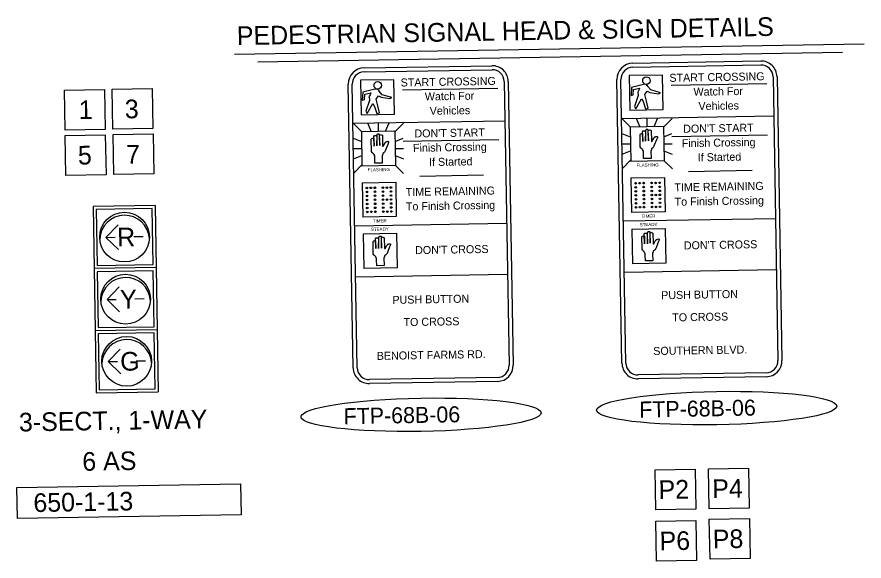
# Model space of a CAD drawing. Extents: x 924596 to 926137, y 853397 to 853834.
# Drawn here: x 925476.3 to 925603.4, y 853695.8 to 853777.4 of the extents above; entities that cross this region are included whole.
import ezdxf

# ---------------------------------------------------------------- set-up
doc = ezdxf.new("R2010")
doc.units = 0
for name, color, linetype in [('NorthArw_dp', 7, 'Continuous'), ('Scale_dp', 7, 'Continuous'), ('SignalHead', 7, 'Continuous'), ('SignPanel', 7, 'Continuous'), ('TextTables', 7, 'Continuous')]:
    doc.layers.add(name, color=color, linetype=linetype)

msp = doc.modelspace()

# ---------------------------------------------------------------- linework, layer by layer
at = {"layer": 'NorthArw_dp'}
for p, q in [((925572.03, 853709.51), (925578.03, 853709.61)), ((925572.14, 853703.51), (925572.03, 853709.51)), ((925578.03, 853709.61), (925578.14, 853703.61)), ((925580.03, 853709.65), (925586.03, 853709.75)), ((925580.14, 853703.65), (925580.03, 853709.65)), ((925586.03, 853709.75), (925586.14, 853703.75)), ((925578.14, 853703.61), (925572.14, 853703.51)), ((925586.14, 853703.75), (925580.14, 853703.65)), ((925572.15, 853701.81), (925578.15, 853701.92)), ((925572.26, 853695.82), (925572.15, 853701.81)), ((925578.15, 853701.92), (925578.26, 853695.92)), ((925580.16, 853702.1), (925586.16, 853702.2)), ((925580.27, 853696.1), (925580.16, 853702.1)), ((925586.16, 853702.2), (925586.26, 853696.2)), ((925586.26, 853696.2), (925580.27, 853696.1)), ((925578.26, 853695.92), (925572.26, 853695.82))]:
    msp.add_line(p, q, dxfattribs=at)
at = {"layer": 'Scale_dp'}
for centre in [(925581.26, 853718.76), (925536.93, 853717.76)]:
    msp.add_ellipse(centre, major_axis=(18, 0.31), ratio=0.138889, dxfattribs=at)
at = {"layer": 'SignalHead'}
for p, q in [((925483.46, 853766.46), (925489.46, 853766.57)), ((925483.57, 853760.47), (925483.46, 853766.46)), ((925489.46, 853766.57), (925489.57, 853760.57)), ((925490.63, 853766.59), (925496.62, 853766.69)), ((925490.73, 853760.59), (925490.63, 853766.59)), ((925496.62, 853766.69), (925496.73, 853760.69)), ((925489.57, 853760.57), (925483.57, 853760.47)), ((925483.58, 853759.65), (925489.58, 853759.76)), ((925483.69, 853753.65), (925483.58, 853759.65)), ((925489.58, 853759.76), (925489.69, 853753.76)), ((925496.73, 853760.69), (925490.73, 853760.59)), ((925490.75, 853759.78), (925496.74, 853759.88)), ((925490.85, 853753.78), (925490.75, 853759.78)), ((925496.74, 853759.88), (925496.85, 853753.88)), ((925489.69, 853753.76), (925483.69, 853753.65)), ((925496.85, 853753.88), (925490.85, 853753.78)), ((925497.05, 853749.15), (925487.74, 853748.99)), ((925487.74, 853748.99), (925488.21, 853721.04)), ((925496.6, 853748.68), (925488.21, 853748.54)), ((925488.21, 853748.54), (925488.35, 853740.15)), ((925496.74, 853740.29), (925496.6, 853748.68)), ((925497.05, 853749.15), (925497.53, 853721.2)), ((925489.68, 853744.37), (925491.51, 853746.26)), ((925489.68, 853744.37), (925491.08, 853744.39)), ((925489.68, 853744.37), (925491.57, 853742.53)), ((925495.27, 853744.46), (925493.87, 853744.44)), ((925497.21, 853739.83), (925487.89, 853739.68)), ((925488.35, 853740.15), (925496.74, 853740.29)), ((925496.75, 853739.36), (925488.37, 853739.22)), ((925488.37, 853739.22), (925488.51, 853730.83)), ((925496.9, 853730.97), (925496.75, 853739.36)), ((925489.84, 853735.05), (925491.67, 853736.94)), ((925489.84, 853735.05), (925491.23, 853735.07)), ((925489.84, 853735.05), (925491.73, 853733.22)), ((925495.43, 853735.14), (925494.03, 853735.12)), ((925497.37, 853730.52), (925488.05, 853730.36)), ((925488.51, 853730.83), (925496.9, 853730.97)), ((925496.91, 853730.04), (925488.53, 853729.9)), ((925488.53, 853729.9), (925488.67, 853721.51)), ((925497.06, 853721.65), (925496.91, 853730.04)), ((925490, 853725.73), (925491.83, 853727.62)), ((925490, 853725.73), (925491.39, 853725.75)), ((925490, 853725.73), (925491.89, 853723.9)), ((925495.59, 853725.82), (925494.19, 853725.8)), ((925488.67, 853721.51), (925497.06, 853721.65)), ((925488.21, 853721.04), (925497.53, 853721.2)), ((925476.33, 853706.85), (925509.88, 853707.42)), ((925509.88, 853707.42), (925509.96, 853702.77)), ((925476.41, 853702.19), (925476.33, 853706.85)), ((925509.96, 853702.77), (925476.41, 853702.19))]:
    msp.add_line(p, q, dxfattribs=at)
for centre in [(925492.47, 853744.41), (925492.63, 853735.1), (925492.79, 853725.78)]:
    msp.add_circle(centre, 3.73, dxfattribs=at)
for centre in [(925492.48, 853743.95), (925492.64, 853734.63), (925492.8, 853725.31)]:
    msp.add_arc(centre, 3.73, 4.5574, 177.3908, dxfattribs=at)
at = {"layer": 'SignPanel'}
for p, q in [((925528.38, 853769.79), (925547.57, 853770.12)), ((925568.67, 853770.49), (925587.87, 853770.83)), ((925568.68, 853769.89), (925587.88, 853770.23)), ((925528.39, 853769.19), (925547.58, 853769.52)), ((925568.14, 853768.64), (925568.23, 853763.45)), ((925589.71, 853768.46), (925590.45, 853725.9)), ((925590.31, 853768.47), (925591.05, 853725.92)), ((925526.76, 853724.79), (925526.02, 853767.35)), ((925527.36, 853724.8), (925526.62, 853767.36)), ((925527.85, 853767.93), (925527.94, 853762.75)), ((925549.41, 853767.75), (925550.15, 853725.2)), ((925550.01, 853767.76), (925550.75, 853725.21)), ((925567.05, 853725.5), (925566.31, 853768.05)), ((925567.65, 853725.51), (925566.91, 853768.06)), ((925574.43, 853767.19), (925588.77, 853767.44)), ((925534.13, 853766.48), (925548.47, 853766.73)), ((925567.02, 853762.18), (925589.81, 853762.58)), ((925567.05, 853762.18), (925568.28, 853760.96)), ((925569.76, 853760.98), (925569.25, 853762.22)), ((925570.83, 853761), (925570.83, 853762.25)), ((925571.91, 853761.02), (925572.43, 853762.28)), ((925573.3, 853760.88), (925574.61, 853762.2)), ((925526.72, 853761.48), (925549.52, 853761.87)), ((925526.75, 853761.48), (925527.98, 853760.25)), ((925529.47, 853760.28), (925528.95, 853761.52)), ((925530.53, 853760.3), (925530.53, 853761.54)), ((925531.61, 853760.32), (925532.13, 853761.57)), ((925533, 853760.18), (925534.31, 853761.49)), ((925568.28, 853760.96), (925573.3, 853761.04)), ((925573.3, 853761.04), (925573.39, 853755.86)), ((925527.98, 853760.25), (925533, 853760.34)), ((925533, 853760.34), (925533.09, 853755.16)), ((925567.05, 853759.97), (925568.3, 853759.45)), ((925573.32, 853759.45), (925574.56, 853759.96)), ((925574.56, 853759.51), (925588.9, 853759.76)), ((925526.76, 853759.26), (925528.01, 853758.75)), ((925533.03, 853758.74), (925534.26, 853759.25)), ((925534.27, 853758.81), (925548.61, 853759.05)), ((925567.08, 853758.4), (925568.32, 853758.41)), ((925573.34, 853758.41), (925574.58, 853758.41)), ((925526.79, 853757.7), (925528.02, 853757.7)), ((925533.05, 853757.71), (925534.29, 853757.71)), ((925567.11, 853756.86), (925568.34, 853757.37)), ((925573.36, 853757.37), (925574.61, 853756.85)), ((925526.81, 853756.16), (925528.04, 853756.67)), ((925533.07, 853756.66), (925534.31, 853756.15)), ((925567.15, 853754.71), (925568.36, 853755.93)), ((925573.39, 853755.86), (925568.37, 853755.77)), ((925573.39, 853755.86), (925574.62, 853754.63)), ((925526.85, 853754.01), (925528.07, 853755.23)), ((925533.09, 853755.16), (925528.07, 853755.07)), ((925533.09, 853755.16), (925534.32, 853753.93)), ((925577.05, 853754.27), (925586.59, 853754.44)), ((925536.76, 853753.57), (925546.3, 853753.73)), ((925568.41, 853753.28), (925573.43, 853753.37)), ((925573.43, 853753.37), (925573.52, 853748.18)), ((925528.11, 853752.57), (925533.13, 853752.66)), ((925533.13, 853752.66), (925533.22, 853747.48)), ((925573.52, 853748.18), (925568.5, 853748.09)), ((925533.22, 853747.48), (925528.2, 853747.39)), ((925567.28, 853746.83), (925590.08, 853747.22)), ((925526.99, 853746.12), (925549.78, 853746.52)), ((925568.54, 853745.6), (925573.56, 853745.69)), ((925573.56, 853745.69), (925573.65, 853740.5)), ((925528.25, 853744.89), (925533.27, 853744.98)), ((925533.27, 853744.98), (925533.36, 853739.8)), ((925573.65, 853740.5), (925568.63, 853740.42)), ((925533.36, 853739.8), (925528.34, 853739.71)), ((925567.42, 853739.15), (925590.21, 853739.54)), ((925527.12, 853738.44), (925549.92, 853738.84)), ((925588.68, 853724.07), (925569.48, 853723.74)), ((925548.38, 853723.37), (925529.19, 853723.04)), ((925548.39, 853722.77), (925529.2, 853722.44)), ((925588.69, 853723.47), (925569.49, 853723.14))]:
    msp.add_line(p, q, dxfattribs=at)
for points in [[(925573.16, 853768.72), (925568.14, 853768.64)], [(925573.25, 853763.54), (925573.16, 853768.72)], [(925532.87, 853768.02), (925527.85, 853767.93)], [(925532.96, 853762.84), (925532.87, 853768.02)], [(925568.23, 853763.45), (925573.25, 853763.54)], [(925527.94, 853762.75), (925532.96, 853762.84)], [(925568.28, 853760.96), (925568.37, 853755.77)], [(925527.98, 853760.25), (925528.07, 853755.07)], [(925568.41, 853753.28), (925568.5, 853748.09)], [(925528.11, 853752.57), (925528.2, 853747.39)], [(925568.54, 853745.6), (925568.63, 853740.42)], [(925528.25, 853744.89), (925528.34, 853739.71)]]:
    msp.add_lwpolyline(points, dxfattribs=at)
for points in [[(925570.69, 853767.33), (925570.31, 853767.32), (925568.49, 853766.86), (925568.42, 853765.66), (925568.75, 853765.76), (925568.79, 853766.57), (925569.7, 853766.73), (925569.65, 853766.59), (925569.61, 853766.44), (925569.42, 853766.15), (925569.42, 853766.01), (925569.47, 853765.91), (925569.47, 853765.82), (925569.48, 853765.67), (925569.48, 853765.63), (925568.93, 853763.98), (925569.13, 853763.65), (925570.01, 853765.16), (925570.26, 853764.73), (925570.61, 853763.63), (925571, 853763.73), (925570.74, 853764.78), (925570.48, 853765.79), (925570.86, 853766.32), (925571.24, 853766.09), (925572.54, 853765.92), (925572.83, 853766.07), (925571.38, 853766.48), (925570.94, 853767), (925570.94, 853767.09), (925570.89, 853767.09), (925570.89, 853767.09)], [(925530.4, 853766.62), (925530.02, 853766.62), (925528.2, 853766.15), (925528.12, 853764.95), (925528.46, 853765.05), (925528.49, 853765.87), (925529.4, 853766.03), (925529.36, 853765.88), (925529.31, 853765.74), (925529.12, 853765.45), (925529.13, 853765.3), (925529.18, 853765.21), (925529.18, 853765.11), (925529.18, 853764.97), (925529.18, 853764.92), (925528.63, 853763.28), (925528.83, 853762.95), (925529.72, 853764.45), (925529.96, 853764.02), (925530.32, 853762.93), (925530.7, 853763.03), (925530.44, 853764.08), (925530.19, 853765.08), (925530.56, 853765.62), (925530.95, 853765.38), (925532.25, 853765.22), (925532.53, 853765.36), (925531.09, 853765.77), (925530.64, 853766.29), (925530.64, 853766.39), (925530.6, 853766.39), (925530.6, 853766.39)], [(925530.02, 853755.48), (925530, 853756.34), (925530, 853756.58), (925529.9, 853756.73), (925529.9, 853756.82), (925529.8, 853756.92), (925529.65, 853757.01), (925529.6, 853757.1), (925529.51, 853757.25), (925529.5, 853757.34), (925529.47, 853759.12), (925529.57, 853759.22), (925529.57, 853759.22), (925529.71, 853759.27), (925529.76, 853759.22), (925529.86, 853759.22), (925529.86, 853759.17), (925529.88, 853758.07), (925529.85, 853759.51), (925529.94, 853759.65), (925530.09, 853759.66), (925530.14, 853759.66), (925530.28, 853759.56), (925530.31, 853758.08), (925530.33, 853759.71), (925530.37, 853759.85), (925530.47, 853759.9), (925530.61, 853759.91), (925530.66, 853759.86), (925530.66, 853759.76), (925530.74, 853758.13), (925530.71, 853759.67), (925530.76, 853759.72), (925530.85, 853759.77), (925531, 853759.82), (925531.05, 853759.72), (925531.14, 853759.68), (925531.17, 853758.14), (925531.17, 853758.04), (925531.17, 853758.04), (925531.27, 853758.05), (925531.27, 853758.05), (925531.55, 853758.53), (925531.64, 853758.63), (925531.64, 853758.68), (925531.69, 853758.72), (925531.78, 853758.73), (925531.83, 853758.77), (925532.02, 853758.78), (925532.07, 853758.73), (925532.07, 853758.73), (925532.07, 853758.68), (925532.07, 853758.64), (925532.07, 853758.59), (925531.94, 853758.3), (925531.61, 853757.47), (925531.57, 853757.33), (925531.43, 853757.14), (925531.33, 853757.04), (925531.19, 853756.94), (925531.19, 853756.84), (925531.1, 853756.6), (925531.12, 853755.5)], [(925570.31, 853756.18), (925570.3, 853757.05), (925570.29, 853757.29), (925570.19, 853757.43), (925570.19, 853757.53), (925570.1, 853757.62), (925569.95, 853757.71), (925569.9, 853757.81), (925569.8, 853757.95), (925569.8, 853758.05), (925569.77, 853759.82), (925569.86, 853759.92), (925569.86, 853759.92), (925570.01, 853759.97), (925570.06, 853759.92), (925570.15, 853759.93), (925570.15, 853759.88), (925570.17, 853758.77), (925570.15, 853760.21), (925570.24, 853760.36), (925570.38, 853760.36), (925570.43, 853760.36), (925570.58, 853760.27), (925570.6, 853758.78), (925570.62, 853760.41), (925570.67, 853760.56), (925570.76, 853760.61), (925570.91, 853760.61), (925570.96, 853760.56), (925570.96, 853760.47), (925571.03, 853758.84), (925571.01, 853760.37), (925571.05, 853760.42), (925571.15, 853760.47), (925571.29, 853760.52), (925571.34, 853760.43), (925571.44, 853760.38), (925571.47, 853758.84), (925571.47, 853758.75), (925571.47, 853758.75), (925571.56, 853758.75), (925571.56, 853758.75), (925571.84, 853759.23), (925571.94, 853759.33), (925571.94, 853759.38), (925571.98, 853759.43), (925572.08, 853759.43), (925572.13, 853759.48), (925572.32, 853759.48), (925572.37, 853759.44), (925572.37, 853759.44), (925572.37, 853759.39), (925572.37, 853759.34), (925572.37, 853759.29), (925572.23, 853759), (925571.91, 853758.18), (925571.86, 853758.03), (925571.72, 853757.84), (925571.63, 853757.74), (925571.49, 853757.64), (925571.49, 853757.55), (925571.4, 853757.31), (925571.42, 853756.2)], [(925530.28, 853740.12), (925530.27, 853740.99), (925530.26, 853741.23), (925530.17, 853741.37), (925530.16, 853741.46), (925530.07, 853741.56), (925529.92, 853741.65), (925529.87, 853741.75), (925529.77, 853741.89), (925529.77, 853741.98), (925529.74, 853743.76), (925529.83, 853743.86), (925529.83, 853743.86), (925529.98, 853743.91), (925530.03, 853743.86), (925530.12, 853743.86), (925530.12, 853743.82), (925530.14, 853742.71), (925530.12, 853744.15), (925530.21, 853744.3), (925530.35, 853744.3), (925530.4, 853744.3), (925530.55, 853744.21), (925530.57, 853742.72), (925530.59, 853744.35), (925530.64, 853744.5), (925530.73, 853744.55), (925530.88, 853744.55), (925530.93, 853744.5), (925530.93, 853744.41), (925531.01, 853742.77), (925530.98, 853744.31), (925531.03, 853744.36), (925531.12, 853744.41), (925531.26, 853744.46), (925531.31, 853744.36), (925531.41, 853744.32), (925531.44, 853742.78), (925531.44, 853742.69), (925531.44, 853742.69), (925531.53, 853742.69), (925531.53, 853742.69), (925531.81, 853743.17), (925531.91, 853743.27), (925531.91, 853743.32), (925531.95, 853743.37), (925532.05, 853743.37), (925532.1, 853743.42), (925532.29, 853743.42), (925532.34, 853743.37), (925532.34, 853743.37), (925532.34, 853743.33), (925532.34, 853743.28), (925532.34, 853743.23), (925532.2, 853742.94), (925531.88, 853742.12), (925531.84, 853741.97), (925531.69, 853741.78), (925531.6, 853741.68), (925531.46, 853741.58), (925531.46, 853741.49), (925531.37, 853741.24), (925531.39, 853740.14)], [(925570.58, 853740.83), (925570.56, 853741.69), (925570.56, 853741.93), (925570.46, 853742.07), (925570.46, 853742.17), (925570.36, 853742.26), (925570.22, 853742.36), (925570.17, 853742.45), (925570.07, 853742.59), (925570.07, 853742.69), (925570.04, 853744.47), (925570.13, 853744.56), (925570.13, 853744.56), (925570.27, 853744.61), (925570.32, 853744.57), (925570.42, 853744.57), (925570.42, 853744.52), (925570.44, 853743.42), (925570.41, 853744.86), (925570.51, 853745), (925570.65, 853745), (925570.7, 853745), (925570.84, 853744.91), (925570.87, 853743.42), (925570.89, 853745.06), (925570.93, 853745.2), (925571.03, 853745.25), (925571.17, 853745.25), (925571.22, 853745.21), (925571.22, 853745.11), (925571.3, 853743.48), (925571.27, 853745.01), (925571.32, 853745.06), (925571.42, 853745.11), (925571.56, 853745.16), (925571.61, 853745.07), (925571.71, 853745.02), (925571.73, 853743.49), (925571.73, 853743.39), (925571.73, 853743.39), (925571.83, 853743.39), (925571.83, 853743.39), (925572.11, 853743.88), (925572.2, 853743.97), (925572.2, 853744.02), (925572.25, 853744.07), (925572.35, 853744.07), (925572.39, 853744.12), (925572.59, 853744.13), (925572.63, 853744.08), (925572.63, 853744.08), (925572.64, 853744.03), (925572.64, 853743.98), (925572.64, 853743.93), (925572.5, 853743.64), (925572.18, 853742.82), (925572.13, 853742.68), (925571.99, 853742.48), (925571.9, 853742.39), (925571.75, 853742.29), (925571.76, 853742.19), (925571.66, 853741.95), (925571.68, 853740.85)]]:
    msp.add_lwpolyline(points, close=True, dxfattribs=at)
for centre, radius in [((925570.73, 853767.89), 0.563), ((925530.44, 853767.18), 0.563), ((925528.81, 853751.79), 0.12), ((925529.41, 853751.8), 0.12), ((925530.01, 853751.81), 0.12), ((925531.21, 853751.83), 0.12), ((925531.81, 853751.84), 0.12), ((925532.41, 853751.85), 0.12), ((925569.11, 853752.49), 0.12), ((925569.12, 853751.89), 0.12), ((925569.71, 853752.5), 0.12), ((925570.31, 853752.51), 0.12), ((925570.32, 853751.91), 0.12), ((925571.51, 853752.53), 0.12), ((925571.52, 853751.93), 0.12), ((925572.11, 853752.54), 0.12), ((925572.71, 853752.55), 0.12), ((925572.72, 853751.95), 0.12), ((925528.82, 853751.19), 0.12), ((925528.83, 853750.59), 0.12), ((925530.02, 853751.21), 0.12), ((925530.03, 853750.61), 0.12), ((925531.22, 853751.23), 0.12), ((925531.23, 853750.63), 0.12), ((925532.42, 853751.25), 0.12), ((925532.43, 853750.65), 0.12), ((925569.13, 853751.29), 0.12), ((925569.14, 853750.69), 0.12), ((925570.33, 853751.31), 0.12), ((925570.34, 853750.71), 0.12), ((925571.53, 853751.33), 0.12), ((925571.54, 853750.73), 0.12), ((925572.14, 853750.74), 0.12), ((925572.73, 853751.35), 0.12), ((925572.74, 853750.75), 0.12), ((925528.84, 853749.99), 0.12), ((925528.85, 853749.39), 0.12), ((925530.04, 853750.01), 0.12), ((925530.05, 853749.41), 0.12), ((925531.24, 853750.03), 0.12), ((925531.25, 853749.43), 0.12), ((925531.84, 853750.04), 0.12), ((925532.44, 853750.05), 0.12), ((925532.45, 853749.45), 0.12), ((925569.15, 853750.09), 0.12), ((925569.16, 853749.49), 0.12), ((925570.35, 853750.11), 0.12), ((925570.36, 853749.51), 0.12), ((925571.55, 853750.13), 0.12), ((925571.56, 853749.53), 0.12), ((925572.75, 853750.15), 0.12), ((925572.76, 853749.55), 0.12), ((925528.86, 853748.79), 0.12), ((925528.87, 853748.19), 0.12), ((925529.47, 853748.2), 0.12), ((925530.06, 853748.81), 0.12), ((925530.07, 853748.21), 0.12), ((925531.26, 853748.83), 0.12), ((925531.27, 853748.23), 0.12), ((925531.87, 853748.24), 0.12), ((925532.46, 853748.85), 0.12), ((925532.47, 853748.25), 0.12), ((925569.17, 853748.89), 0.12), ((925569.77, 853748.9), 0.12), ((925570.37, 853748.91), 0.12), ((925571.57, 853748.93), 0.12), ((925572.17, 853748.94), 0.12), ((925572.77, 853748.95), 0.12)]:
    msp.add_circle(centre, radius, dxfattribs=at)
for centre, radius, start, end in [((925528.42, 853767.39), 2.4, 90.9946, 180.9946), ((925547.61, 853767.72), 2.4, 0.9946, 90.9946), ((925568.71, 853768.09), 2.4, 90.9946, 180.9946), ((925568.71, 853768.09), 1.8, 90.9946, 180.9946), ((925587.91, 853768.43), 2.4, 0.9946, 90.9946), ((925587.91, 853768.43), 1.8, 0.9946, 90.9946), ((925528.42, 853767.39), 1.8, 90.9946, 180.9946), ((925547.61, 853767.72), 1.8, 0.9946, 90.9946), ((925548.35, 853725.17), 2.4, 270.9946, 0.9946), ((925569.45, 853725.54), 2.4, 180.9946, 270.9946), ((925569.45, 853725.54), 1.8, 180.9946, 270.9946), ((925588.65, 853725.87), 1.8, 270.9946, 0.9946), ((925588.65, 853725.87), 2.4, 270.9946, 0.9946), ((925529.16, 853724.84), 2.4, 180.9946, 270.9946), ((925529.16, 853724.84), 1.8, 180.9946, 270.9946), ((925548.35, 853725.17), 1.8, 270.9946, 0.9946)]:
    msp.add_arc(centre, radius, start, end, dxfattribs=at)
at = {"layer": 'TextTables'}
for p, q in [((925508.98, 853771.83), (925603.36, 853773.43)), ((925512.47, 853770.68), (925600.12, 853772.17))]:
    msp.add_line(p, q, dxfattribs=at)

# ---------------------------------------------------------------- texts
at = {"layer": 'NorthArw_dp'}
for s, p in [('P2', (925572.57, 853705.12)), ('P4', (925580.62, 853705.26)), ('P6', (925572.72, 853697.42)), ('P8', (925580.7, 853697.71))]:
    msp.add_text(s, height=2.8, rotation=0.9946, dxfattribs=at).set_placement(p)
at = {"layer": 'Scale_dp'}
for p in [(925525.34, 853716.34), (925569.67, 853717.34)]:
    msp.add_text('FTP-68B-06', height=2.4, rotation=0.9946, dxfattribs=at).set_placement(p)
at = {"layer": 'SignalHead'}
for s, height, rotation, p in [('1', 2.8, 0.9946, (925485.62, 853762.1)), ('3', 2.8, 0.9946, (925492.53, 853762.22)), ('7', 2.8, 0.9946, (925492.72, 853755.41)), ('5', 2.8, 0.9946, (925485.5, 853755.29)), ('R', 2.8, 0.9741, (925491.38, 853743)), ('Y', 2.8, 0.9741, (925491.82, 853733.68)), ('G', 2.8, 0.9741, (925491.84, 853724.36)), ('3-SECT., 1-WAY', 2.796, 0.9741, (925476.66, 853715.25)), (' 6 AS ', 2.796, 0.9741, (925485.12, 853709.33)), ('  650-1-13  ', 2.796, 0.9741, (925476.75, 853703.13))]:
    msp.add_text(s, height=height, rotation=rotation, dxfattribs=at).set_placement(p)
at = {"layer": 'SignPanel'}
for s, height, p in [('START CROSSING', 1.2009, (925533.88, 853767)), ('START CROSSING', 1.2009, (925574.18, 853767.7)), ('Watch For', 1.201, (925537.51, 853764.9)), ('Watch For', 1.201, (925577.8, 853765.6)), ('Vehicles', 1.201, (925578.54, 853763.46)), ('Vehicles', 1.201, (925538.24, 853762.75)), ("DON'T START", 1.2009, (925576.25, 853760.06)), ("DON'T START", 1.2009, (925535.95, 853759.35)), ('Finish Crossing', 1.2009, (925535.73, 853757.19)), ('Finish Crossing', 1.2009, (925576.03, 853757.89)), ('If Started', 1.201, (925578.44, 853755.77)), ('If Started', 1.201, (925538.14, 853755.07)), ('FLASHING', 0.48, (925528.95, 853754.26)), ('FLASHING', 0.48, (925569.25, 853754.96)), ('TIME REMAINING', 1.2009, (925534.64, 853750.57)), ('TIME REMAINING', 1.2009, (925574.93, 853751.27)), ('To Finish Crossing', 1.2009, (925534.67, 853748.41)), ('To Finish Crossing', 1.2009, (925574.97, 853749.11)), ('TIMER', 0.48, (925529.71, 853746.59)), ('TIMER', 0.48, (925570.01, 853747.3)), ('STEADY', 0.48, (925529.43, 853745.34)), ('STEADY', 0.48, (925569.73, 853746.04)), ("DON'T CROSS", 1.2009, (925536.05, 853741.85)), ("DON'T CROSS", 1.2009, (925576.35, 853742.56)), ('PUSH BUTTON', 1.2009, (925532.65, 853734.39)), ('PUSH BUTTON', 1.2009, (925572.95, 853735.09)), ('TO CROSS', 1.201, (925574.61, 853731.76)), ('TO CROSS', 1.201, (925534.31, 853731.05)), ('SOUTHERN BLVD.', 1.2009, (925571.76, 853726.72)), ('BENOIST FARMS RD.', 1.2009, (925530.3, 853725.99))]:
    msp.add_text(s, height=height, rotation=0.9946, dxfattribs=at).set_placement(p)
at = {"layer": 'TextTables'}
msp.add_text('PEDESTRIAN SIGNAL HEAD & SIGN DETAILS', height=2.8001, rotation=0.9944, dxfattribs=at).set_placement((925509.33, 853773.21))

doc.saveas('drawing.dxf')
